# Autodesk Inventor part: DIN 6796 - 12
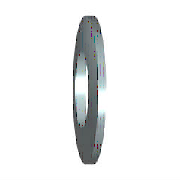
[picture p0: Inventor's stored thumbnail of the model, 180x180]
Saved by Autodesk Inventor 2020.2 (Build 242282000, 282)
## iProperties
IsCustomPart: 0
Manager: www.cadconsulting.pl
Company: Fabian Stasiak CAD Consulting
Created: 2010-02
Part Number: DIN 6796 - 12
Material: Stal, miękka
Description: Podkładka sprężysta stożkowa
Document SubType Name: Modeling
Standard: DIN 6796
Designer: F.Stasiak
Standard Revision: 1987
Standards Organization: DIN
Language: pl-PL
Size Designation: 12
Categories: <MemberInstance><Categories><Category DisplayName="Mocowania" InternalName="e4da775c-781d-43d5-af7c-5136215cf5a6" Mnemonic="FSTN"><Category DisplayName="Podkład
Density: 1 g/cm^3
Appearance: Stal
Author: F.Stasiak
Subject: Zbiór ćwiczeń. Autodesk Inventor 2020. Kurs podstawowy
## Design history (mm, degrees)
sketch "Sketch"
  geometry: C1 r 14.5 at (0, 0); C2 r 6.5 at (0, 0); 1 further point
  constraints: 2 centre point, 2 coincident
  dimensions: "d0" = 13 diameter of C2 (= SD1); "d1" = 29 diameter of C1 (= SD2)
extrude "Body" new body sketch "Sketch" distance "d2" = 3 (= SD); taper "d3" = 0 deg
workaxis "Work Axis1"
workplane "Work Plane1"
body "Solid1"
other parameters: "SD1" = 13 [user parameter; used in 1 equation term], "SD2" = 29 [user parameter; used in 1 equation term], "SD" = 3 [user parameter; used in 1 equation term], "d4" = 0, "d5" = 0, "d6" = 0, "d7" = 0, "NND" = 12 [user parameter]
